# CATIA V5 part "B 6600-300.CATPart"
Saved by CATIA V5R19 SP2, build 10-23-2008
Part number: B 6600-300
Bounding box of the stored display mesh (mm): x -59.975 to 59.975, y -59.975 to 59.975, z 0 to 740
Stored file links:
  C:\Users\Bora\Desktop\3D Katı model\B serisi\B 6600\B 6600-300.CATPart
  C:\Program Files\Dassault Systemes\B19\intel_a\reffiles\standard\MetricThickPitch.txt
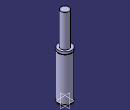
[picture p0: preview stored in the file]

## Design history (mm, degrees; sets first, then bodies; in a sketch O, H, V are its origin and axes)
Body1 (main body)
  Sketch1 on yz-plane, origin (0, 0, 0), H (0, 1, 0), V (0, 0, 1)
    point P3 (37.5, 739)
    point P5 (37.5, 739)
    point P10 (60, 412)
    point P11 (60, 417)
    point P13 (60, 417)
    point P14 (60, 412)
    line L1 (60, 0) -> (60, 8)
    line L2 (37.5, 739) -> (37.5, 437)
    arc A1 centre (36.5, 739) radius 1 from (37.5, 739) to (36.5, 740) ccw
    line L3 (56, 13) -> (56, 8)
    line L4 (60, 13) -> (60, 412)
    line L5 (60, 417) -> (60, 437)
    arc A2 centre (60, 414.5) radius 2.5 from (60, 417) to (60, 412) ccw
    line L6 (60, 0) -> (0, 0)
    line L7 (56, 8) -> (60, 8)
    line L8 (56, 13) -> (60, 13)
    line L9 (37.5, 437) -> (60, 437)
    line L10 (36.5, 740) -> (0, 740)
    point P15 (0, 740)
    horizontal: L6 H, L7 H, L8 H, L9 H
    coincidence: P15 V, P3 P5, P10 P14, P11 P13
    tangency: L10 A1
  Shaft1: profile Sketch1, axis Sketch1.V, angle 360
  Sketch2 on face of Shaft1 from Sketch1.L6, origin (0, 0, 0), H (1, 0, 0), V (0, -1, 0)
    point P1 (40, 0)
    distance V P1 = 40
  Hole1: placed by Sketch2, at (40, 0, 0) direction (0, 0, 1), diameter 8.376, depth 16, threaded "M10", thread diameter 10, thread depth 16, pitch 1.5
  CircPattern1: of Hole1, instances 4, angular step 90, axis from xy-plane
